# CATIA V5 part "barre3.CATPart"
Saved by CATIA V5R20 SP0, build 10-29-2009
Part number: barre3
Bounding box of the stored display mesh (mm): x -10 to 0, y 275.002 to 380.432, z -25 to 307.775
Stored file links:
  D:\Dropbox\IAO_2012\IAO_2012_748_omeyer\omeyer\omeyer\barre3.CATPart
  U:\Projet IAO\omeyer\Catia\Ass_748_skl.CATProduct
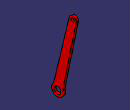
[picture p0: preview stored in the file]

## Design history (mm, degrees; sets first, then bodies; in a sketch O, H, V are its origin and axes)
Set1
  Plane1 "PlanRef": linked copy from another document
  DatumPoint1 "PointC": linked copy from another document
  Point1 "PointD": linked copy from another document
Body1 (main body)
  Sketch1 on Plane1, origin (0, 0, 0), H (0, 1, 0), V (0, 0, 1)
    circle A1 centre (365.4338, 292.7771) radius 7.5
    point P1 (365.4338, 292.7771)
    circle A2 centre (300, 0) radius 15
    point P2 (300, 0)
    arc A3 centre (365.4338, 292.7771) radius 15 from (380.1251, 289.7498) to (350.8515, 296.2923) ccw
    arc A4 centre (300, 0) radius 25 from (284.0722, 19.2692) to (322.6157, 10.655) ccw
    reference projected point E1 (300, 0) from Point1
    reference projected point E2 (300, 0) from Point1
    reference projected point E3 (365.4338, 292.7771) from DatumPoint1
    reference projected point E4 (365.4338, 292.7771) from DatumPoint1
    line L1 (350.8515, 296.2923) -> (284.0722, 19.2692)
    line L2 (380.1251, 289.7498) -> (322.6157, 10.655)
    reference projected point E5 (300, 0) from Point1
    reference projected point E6 (300, 0) from Point1
    radius A1 = 7.5
    radius A3 = 15
    radius A4 = 25
    radius A2 = 15
    distance L2 E5 = 20
    distance E6 L1 = 20
    coincidence: P2 E1, P1 E3
    concentricity: A4 E2, A3 E4
    tangency: L2 A3, L1 A3
  Pad1: profile Sketch1, direction (-1, 0, 0), length 10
